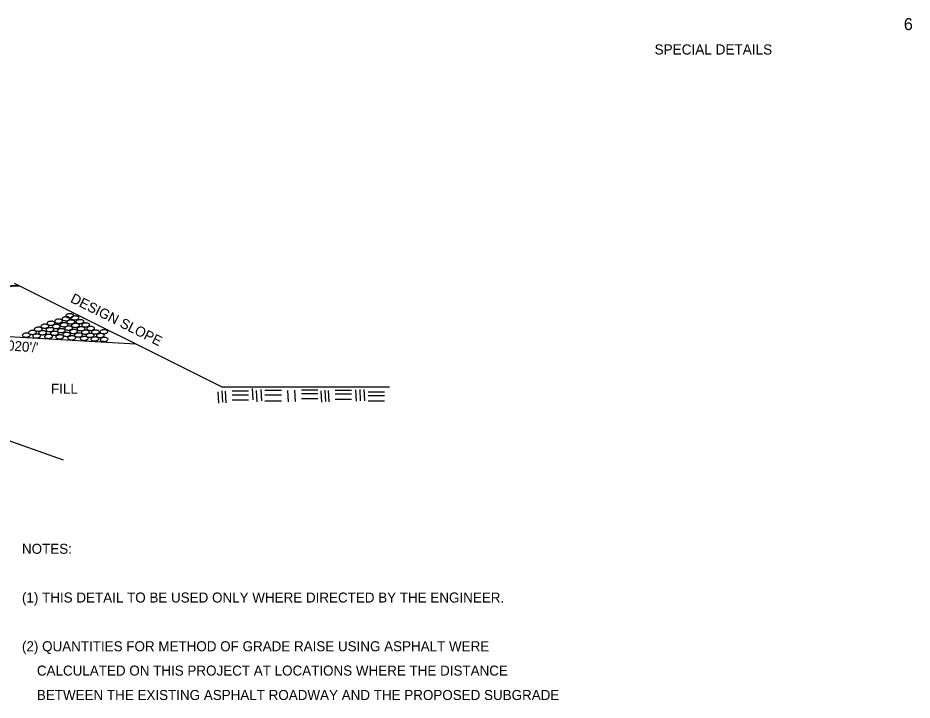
# Model space of a CAD drawing. Extents: x 3287 to 1767681, y -265 to 581440.
# Drawn here: x 3460.9 to 3567.9, y 19.6 to 101.2 of the extents above; entities that cross this region are included whole.
import ezdxf

# ---------------------------------------------------------------- set-up
doc = ezdxf.new("R2010")
doc.units = 0
for name, color, linetype in [('R_Border Notes', 7, 'Continuous'), ('R_Border PE', 7, 'Continuous'), ('R_Border Prem', 7, 'Continuous')]:
    doc.layers.add(name, color=color, linetype=linetype)

msp = doc.modelspace()

# ---------------------------------------------------------------- linework, layer by layer
at = {"layer": 'R_Border PE'}
for p, q in [((3331.63, 63.99), (3461.08, 69.15)), ((3331.8, 64.08), (3460.94, 69.23)), ((3485.32, 57.03), (3460.48, 69.45)), ((3444.21, 64.01), (3474.97, 62.21)), ((3431.52, 60.73), (3466.29, 48.36)), ((3505.34, 57.03), (3485.32, 57.03)), ((3488.92, 56.89), (3488.99, 55.54)), ((3489.95, 56.78), (3490.03, 55.42)), ((3501.28, 56.73), (3501.36, 55.38)), ((3501.77, 56.78), (3501.84, 55.43)), ((3502.28, 56.78), (3502.36, 55.43)), ((3484.81, 56.5), (3484.89, 55.15)), ((3485.28, 56.59), (3485.36, 55.24)), ((3485.69, 56.55), (3485.76, 55.19)), ((3488.47, 56.55), (3486.51, 56.55)), ((3488.47, 56.1), (3486.51, 56.1)), ((3489.37, 56.66), (3489.45, 55.31)), ((3492.4, 56.66), (3490.43, 56.66)), ((3492.4, 56.08), (3490.43, 56.08)), ((3493.12, 56.65), (3493.2, 55.29)), ((3493.99, 56.7), (3494.07, 55.34)), ((3496.78, 56.7), (3494.82, 56.7)), ((3496.78, 56.24), (3494.82, 56.24)), ((3496.78, 55.64), (3494.82, 55.64)), ((3497.13, 56.59), (3497.21, 55.24)), ((3497.6, 56.68), (3497.67, 55.33)), ((3498, 56.64), (3498.08, 55.28)), ((3500.79, 56.64), (3498.83, 56.64)), ((3500.79, 56.19), (3498.83, 56.19)), ((3504.74, 56.43), (3502.78, 56.43)), ((3504.74, 55.99), (3502.78, 55.99)), ((3488.47, 55.49), (3486.51, 55.49)), ((3492.4, 55.39), (3490.43, 55.39)), ((3500.79, 55.58), (3498.83, 55.58)), ((3504.74, 55.38), (3502.78, 55.38))]:
    msp.add_line(p, q, dxfattribs=at)
for points in [[(3466.63, 64.99), (3466.47, 65.01), (3466.27, 65.06), (3466.17, 65.15), (3466.16, 65.21), (3466.21, 65.31), (3466.26, 65.36), (3466.37, 65.42), (3466.53, 65.46), (3466.62, 65.46), (3466.74, 65.45), (3466.88, 65.44), (3466.99, 65.4), (3467.08, 65.3), (3467.1, 65.25), (3467.07, 65.15), (3466.99, 65.1), (3466.92, 65.06), (3466.8, 65.01), (3466.74, 64.99), (3466.63, 64.99)], [(3467.08, 65.36), (3466.91, 65.38), (3466.72, 65.43), (3466.63, 65.53), (3466.61, 65.58), (3466.66, 65.69), (3466.71, 65.73), (3466.82, 65.79), (3466.98, 65.83), (3467.06, 65.83), (3467.19, 65.83), (3467.33, 65.82), (3467.43, 65.76), (3467.54, 65.68), (3467.55, 65.61), (3467.52, 65.52), (3467.45, 65.46), (3467.37, 65.43), (3467.26, 65.39), (3467.19, 65.36), (3467.08, 65.36)], [(3467.72, 65.09), (3467.55, 65.11), (3467.35, 65.16), (3467.25, 65.26), (3467.24, 65.31), (3467.29, 65.41), (3467.35, 65.45), (3467.46, 65.52), (3467.62, 65.56), (3467.7, 65.56), (3467.83, 65.55), (3467.96, 65.54), (3468.07, 65.49), (3468.17, 65.41), (3468.18, 65.34), (3468.15, 65.26), (3468.08, 65.19), (3468, 65.15), (3467.89, 65.12), (3467.83, 65.1), (3467.72, 65.09)], [(3463.32, 63.74), (3463.15, 63.76), (3462.95, 63.81), (3462.86, 63.91), (3462.84, 63.97), (3462.89, 64.07), (3462.94, 64.11), (3463.05, 64.17), (3463.21, 64.22), (3463.3, 64.22), (3463.42, 64.21), (3463.56, 64.2), (3463.66, 64.14), (3463.77, 64.06), (3463.78, 63.99), (3463.76, 63.91), (3463.68, 63.84), (3463.61, 63.81), (3463.49, 63.77), (3463.42, 63.75), (3463.32, 63.74)], [(3464.12, 64.1), (3463.95, 64.12), (3463.75, 64.17), (3463.65, 64.26), (3463.64, 64.32), (3463.68, 64.42), (3463.75, 64.47), (3463.86, 64.54), (3464.02, 64.57), (3464.1, 64.57), (3464.22, 64.56), (3464.36, 64.55), (3464.47, 64.51), (3464.56, 64.41), (3464.58, 64.36), (3464.54, 64.26), (3464.47, 64.2), (3464.4, 64.17), (3464.3, 64.13), (3464.23, 64.11), (3464.12, 64.1)], [(3464.83, 64.45), (3464.67, 64.47), (3464.47, 64.53), (3464.38, 64.62), (3464.36, 64.68), (3464.41, 64.78), (3464.47, 64.83), (3464.57, 64.89), (3464.73, 64.92), (3464.82, 64.92), (3464.94, 64.93), (3465.08, 64.9), (3465.19, 64.85), (3465.29, 64.77), (3465.3, 64.71), (3465.28, 64.61), (3465.2, 64.55), (3465.13, 64.52), (3465.01, 64.48), (3464.94, 64.46), (3464.83, 64.45)], [(3465.48, 64.06), (3465.31, 64.08), (3465.12, 64.13), (3465.02, 64.23), (3465, 64.28), (3465.05, 64.39), (3465.11, 64.43), (3465.21, 64.5), (3465.37, 64.53), (3465.46, 64.53), (3465.59, 64.54), (3465.73, 64.52), (3465.83, 64.46), (3465.93, 64.38), (3465.94, 64.32), (3465.92, 64.22), (3465.84, 64.16), (3465.76, 64.12), (3465.65, 64.09), (3465.59, 64.07), (3465.48, 64.06)], [(3465.76, 64.71), (3465.59, 64.72), (3465.39, 64.78), (3465.29, 64.87), (3465.28, 64.93), (3465.33, 65.03), (3465.38, 65.08), (3465.49, 65.14), (3465.65, 65.18), (3465.74, 65.18), (3465.86, 65.17), (3466, 65.16), (3466.1, 65.12), (3466.2, 65.02), (3466.22, 64.96), (3466.18, 64.87), (3466.11, 64.81), (3466.03, 64.78), (3465.93, 64.73), (3465.86, 64.71), (3465.76, 64.71)], [(3466.42, 64.27), (3466.25, 64.29), (3466.05, 64.35), (3465.95, 64.43), (3465.94, 64.49), (3465.99, 64.59), (3466.04, 64.64), (3466.17, 64.7), (3466.32, 64.74), (3466.4, 64.74), (3466.53, 64.73), (3466.66, 64.72), (3466.77, 64.68), (3466.86, 64.58), (3466.88, 64.53), (3466.85, 64.43), (3466.78, 64.38), (3466.7, 64.34), (3466.6, 64.3), (3466.53, 64.28), (3466.42, 64.27)], [(3466.95, 63.87), (3466.79, 63.89), (3466.59, 63.95), (3466.49, 64.04), (3466.48, 64.1), (3466.53, 64.2), (3466.58, 64.24), (3466.69, 64.3), (3466.85, 64.35), (3466.93, 64.35), (3467.06, 64.34), (3467.2, 64.33), (3467.31, 64.27), (3467.41, 64.19), (3467.42, 64.12), (3467.39, 64.03), (3467.32, 63.97), (3467.24, 63.95), (3467.13, 63.9), (3467.06, 63.88), (3466.95, 63.87)], [(3467.22, 64.62), (3467.05, 64.63), (3466.85, 64.68), (3466.75, 64.78), (3466.74, 64.84), (3466.79, 64.94), (3466.85, 64.98), (3466.96, 65.04), (3467.12, 65.09), (3467.2, 65.09), (3467.33, 65.07), (3467.47, 65.07), (3467.57, 65.01), (3467.67, 64.93), (3467.68, 64.86), (3467.65, 64.78), (3467.57, 64.71), (3467.5, 64.68), (3467.4, 64.64), (3467.33, 64.62), (3467.22, 64.62)], [(3467.78, 64.19), (3467.61, 64.21), (3467.42, 64.26), (3467.32, 64.36), (3467.3, 64.41), (3467.35, 64.52), (3467.41, 64.56), (3467.52, 64.62), (3467.68, 64.67), (3467.76, 64.67), (3467.89, 64.65), (3468.03, 64.65), (3468.13, 64.59), (3468.23, 64.51), (3468.25, 64.44), (3468.22, 64.36), (3468.14, 64.29), (3468.07, 64.26), (3467.95, 64.22), (3467.89, 64.2), (3467.78, 64.19)], [(3468.32, 64.65), (3468.14, 64.67), (3467.95, 64.71), (3467.84, 64.81), (3467.83, 64.86), (3467.88, 64.97), (3467.94, 65.01), (3468.05, 65.08), (3468.21, 65.12), (3468.29, 65.12), (3468.42, 65.11), (3468.56, 65.1), (3468.67, 65.05), (3468.76, 64.97), (3468.78, 64.9), (3468.74, 64.81), (3468.67, 64.74), (3468.6, 64.71), (3468.49, 64.68), (3468.42, 64.65), (3468.32, 64.65)], [(3468.42, 64.27), (3468.6, 64.25), (3468.79, 64.2), (3468.9, 64.1), (3468.91, 64.05), (3468.86, 63.95), (3468.8, 63.9), (3468.68, 63.84), (3468.53, 63.8), (3468.44, 63.8), (3468.32, 63.81), (3468.18, 63.82), (3468.08, 63.86), (3467.98, 63.96), (3467.97, 64.02), (3468, 64.11), (3468.07, 64.17), (3468.14, 64.2), (3468.25, 64.24), (3468.32, 64.26), (3468.42, 64.27)], [(3468.98, 64.73), (3469.14, 64.71), (3469.34, 64.67), (3469.44, 64.57), (3469.46, 64.52), (3469.41, 64.41), (3469.35, 64.37), (3469.23, 64.3), (3469.08, 64.26), (3469, 64.26), (3468.87, 64.27), (3468.73, 64.28), (3468.62, 64.33), (3468.53, 64.42), (3468.52, 64.48), (3468.55, 64.57), (3468.62, 64.64), (3468.69, 64.67), (3468.8, 64.7), (3468.87, 64.73), (3468.98, 64.73)], [(3469.58, 64.31), (3469.75, 64.3), (3469.94, 64.24), (3470.05, 64.15), (3470.06, 64.1), (3470.01, 63.99), (3469.96, 63.95), (3469.84, 63.88), (3469.69, 63.84), (3469.6, 63.84), (3469.47, 63.85), (3469.33, 63.86), (3469.23, 63.91), (3469.13, 63.99), (3469.12, 64.07), (3469.15, 64.15), (3469.22, 64.22), (3469.29, 64.25), (3469.41, 64.28), (3469.47, 64.31), (3469.58, 64.31)], [(3461.88, 63.03), (3461.72, 63.05), (3461.52, 63.09), (3461.43, 63.2), (3461.41, 63.25), (3461.46, 63.36), (3461.51, 63.4), (3461.62, 63.46), (3461.79, 63.5), (3461.86, 63.5), (3461.99, 63.49), (3462.13, 63.48), (3462.24, 63.43), (3462.34, 63.35), (3462.35, 63.28), (3462.32, 63.19), (3462.25, 63.13), (3462.17, 63.09), (3462.06, 63.06), (3461.99, 63.03), (3461.88, 63.03)], [(3462.62, 63.36), (3462.45, 63.37), (3462.26, 63.42), (3462.16, 63.52), (3462.15, 63.57), (3462.2, 63.68), (3462.25, 63.72), (3462.36, 63.78), (3462.52, 63.82), (3462.6, 63.82), (3462.73, 63.82), (3462.87, 63.81), (3462.97, 63.76), (3463.07, 63.67), (3463.09, 63.61), (3463.06, 63.51), (3462.99, 63.46), (3462.9, 63.42), (3462.79, 63.37), (3462.73, 63.36), (3462.62, 63.36)], [(3463.13, 62.93), (3462.96, 62.95), (3462.76, 63), (3462.67, 63.09), (3462.65, 63.16), (3462.71, 63.26), (3462.75, 63.31), (3462.87, 63.36), (3463.03, 63.4), (3463.11, 63.4), (3463.23, 63.39), (3463.37, 63.38), (3463.48, 63.34), (3463.58, 63.25), (3463.6, 63.19), (3463.56, 63.09), (3463.49, 63.04), (3463.42, 63), (3463.3, 62.96), (3463.23, 62.94), (3463.13, 62.93)], [(3463.84, 63.32), (3463.67, 63.33), (3463.48, 63.38), (3463.38, 63.48), (3463.36, 63.53), (3463.42, 63.64), (3463.46, 63.68), (3463.58, 63.75), (3463.74, 63.79), (3463.82, 63.79), (3463.94, 63.78), (3464.08, 63.77), (3464.19, 63.72), (3464.29, 63.63), (3464.31, 63.57), (3464.28, 63.48), (3464.2, 63.42), (3464.13, 63.38), (3464.02, 63.34), (3463.94, 63.32), (3463.84, 63.32)], [(3464.55, 62.87), (3464.38, 62.89), (3464.19, 62.95), (3464.09, 63.04), (3464.08, 63.09), (3464.13, 63.2), (3464.18, 63.24), (3464.29, 63.31), (3464.45, 63.35), (3464.53, 63.35), (3464.66, 63.34), (3464.79, 63.33), (3464.9, 63.28), (3465, 63.2), (3465.02, 63.13), (3464.99, 63.04), (3464.91, 62.97), (3464.84, 62.94), (3464.72, 62.9), (3464.66, 62.88), (3464.55, 62.87)], [(3464.72, 63.69), (3464.54, 63.71), (3464.35, 63.76), (3464.26, 63.86), (3464.24, 63.91), (3464.29, 64.02), (3464.34, 64.07), (3464.46, 64.12), (3464.61, 64.16), (3464.7, 64.16), (3464.82, 64.15), (3464.96, 64.14), (3465.07, 64.1), (3465.17, 64.01), (3465.18, 63.95), (3465.15, 63.85), (3465.08, 63.8), (3465, 63.76), (3464.89, 63.72), (3464.82, 63.69), (3464.72, 63.69)], [(3465.27, 63.25), (3465.1, 63.27), (3464.9, 63.33), (3464.79, 63.42), (3464.78, 63.48), (3464.83, 63.58), (3464.89, 63.62), (3465, 63.69), (3465.16, 63.72), (3465.24, 63.72), (3465.37, 63.72), (3465.51, 63.7), (3465.61, 63.66), (3465.71, 63.57), (3465.73, 63.51), (3465.69, 63.42), (3465.62, 63.36), (3465.54, 63.32), (3465.44, 63.29), (3465.37, 63.26), (3465.27, 63.25)], [(3465.88, 63.29), (3466.04, 63.29), (3466.24, 63.22), (3466.34, 63.13), (3466.35, 63.07), (3466.3, 62.96), (3466.24, 62.92), (3466.14, 62.87), (3465.97, 62.82), (3465.89, 62.82), (3465.76, 62.83), (3465.63, 62.86), (3465.52, 62.9), (3465.43, 62.97), (3465.41, 63.04), (3465.44, 63.13), (3465.52, 63.19), (3465.59, 63.24), (3465.7, 63.27), (3465.77, 63.29), (3465.88, 63.29)], [(3466.08, 63.57), (3465.92, 63.58), (3465.72, 63.64), (3465.62, 63.73), (3465.61, 63.79), (3465.66, 63.89), (3465.72, 63.95), (3465.82, 64), (3465.98, 64.03), (3466.06, 64.03), (3466.19, 64.04), (3466.33, 64.02), (3466.43, 63.97), (3466.53, 63.88), (3466.55, 63.82), (3466.52, 63.72), (3466.44, 63.67), (3466.37, 63.63), (3466.26, 63.6), (3466.19, 63.57), (3466.08, 63.57)], [(3466.7, 63.59), (3466.87, 63.58), (3467.07, 63.52), (3467.17, 63.42), (3467.18, 63.36), (3467.13, 63.26), (3467.07, 63.22), (3466.96, 63.17), (3466.8, 63.12), (3466.72, 63.11), (3466.59, 63.13), (3466.46, 63.15), (3466.35, 63.2), (3466.25, 63.27), (3466.24, 63.34), (3466.27, 63.43), (3466.34, 63.49), (3466.41, 63.53), (3466.53, 63.57), (3466.6, 63.58), (3466.7, 63.59)], [(3467.32, 63.19), (3467.48, 63.17), (3467.68, 63.1), (3467.78, 63.02), (3467.8, 62.96), (3467.74, 62.86), (3467.68, 62.81), (3467.57, 62.74), (3467.42, 62.71), (3467.33, 62.71), (3467.21, 62.7), (3467.07, 62.73), (3466.96, 62.78), (3466.86, 62.86), (3466.85, 62.92), (3466.88, 63.02), (3466.95, 63.08), (3467.03, 63.11), (3467.14, 63.15), (3467.21, 63.17), (3467.32, 63.19)], [(3467.53, 63.93), (3467.7, 63.93), (3467.9, 63.85), (3468, 63.76), (3468.01, 63.7), (3467.96, 63.61), (3467.91, 63.56), (3467.8, 63.51), (3467.63, 63.47), (3467.55, 63.46), (3467.42, 63.47), (3467.29, 63.49), (3467.18, 63.53), (3467.08, 63.61), (3467.07, 63.67), (3467.1, 63.77), (3467.18, 63.83), (3467.25, 63.88), (3467.36, 63.91), (3467.43, 63.93), (3467.53, 63.93)], [(3468.11, 63.52), (3468.28, 63.51), (3468.48, 63.45), (3468.58, 63.36), (3468.6, 63.31), (3468.54, 63.2), (3468.49, 63.16), (3468.37, 63.08), (3468.22, 63.06), (3468.13, 63.06), (3468, 63.06), (3467.87, 63.07), (3467.76, 63.12), (3467.67, 63.21), (3467.65, 63.27), (3467.68, 63.36), (3467.76, 63.42), (3467.83, 63.46), (3467.94, 63.49), (3468, 63.51), (3468.11, 63.52)], [(3468.94, 63.86), (3469.11, 63.85), (3469.31, 63.79), (3469.42, 63.69), (3469.43, 63.64), (3469.38, 63.54), (3469.32, 63.5), (3469.2, 63.44), (3469.04, 63.39), (3468.96, 63.39), (3468.83, 63.4), (3468.7, 63.42), (3468.59, 63.46), (3468.5, 63.54), (3468.48, 63.61), (3468.52, 63.7), (3468.58, 63.76), (3468.65, 63.8), (3468.76, 63.84), (3468.83, 63.86), (3468.94, 63.86)], [(3469.51, 63.48), (3469.69, 63.47), (3469.88, 63.41), (3469.98, 63.32), (3469.99, 63.26), (3469.94, 63.16), (3469.88, 63.11), (3469.77, 63.06), (3469.62, 63.01), (3469.54, 63.01), (3469.41, 63.03), (3469.27, 63.03), (3469.17, 63.08), (3469.06, 63.17), (3469.05, 63.23), (3469.08, 63.32), (3469.16, 63.38), (3469.23, 63.42), (3469.34, 63.46), (3469.41, 63.48), (3469.51, 63.48)], [(3470.15, 63.88), (3470.31, 63.86), (3470.51, 63.81), (3470.61, 63.72), (3470.63, 63.66), (3470.57, 63.56), (3470.51, 63.51), (3470.4, 63.45), (3470.24, 63.41), (3470.16, 63.41), (3470.04, 63.42), (3469.9, 63.43), (3469.79, 63.48), (3469.7, 63.57), (3469.69, 63.63), (3469.71, 63.72), (3469.79, 63.78), (3469.86, 63.81), (3469.97, 63.86), (3470.04, 63.88), (3470.15, 63.88)], [(3470.74, 63.46), (3470.9, 63.45), (3471.1, 63.39), (3471.2, 63.3), (3471.21, 63.24), (3471.16, 63.14), (3471.11, 63.09), (3471, 63.04), (3470.84, 62.99), (3470.76, 62.99), (3470.63, 63), (3470.49, 63.02), (3470.39, 63.06), (3470.29, 63.14), (3470.27, 63.21), (3470.3, 63.3), (3470.38, 63.36), (3470.46, 63.4), (3470.56, 63.44), (3470.63, 63.46), (3470.74, 63.46)], [(3471.18, 63.44), (3471.01, 63.46), (3470.82, 63.51), (3470.72, 63.61), (3470.7, 63.66), (3470.76, 63.77), (3470.81, 63.81), (3470.92, 63.87), (3471.07, 63.91), (3471.16, 63.91), (3471.29, 63.91), (3471.43, 63.89), (3471.53, 63.84), (3471.63, 63.76), (3471.65, 63.69), (3471.62, 63.6), (3471.54, 63.54), (3471.47, 63.51), (3471.35, 63.47), (3471.29, 63.44), (3471.18, 63.44)], [(3468.81, 63.11), (3468.98, 63.09), (3469.17, 63.04), (3469.27, 62.95), (3469.29, 62.89), (3469.23, 62.79), (3469.18, 62.74), (3469.06, 62.69), (3468.91, 62.64), (3468.83, 62.64), (3468.71, 62.65), (3468.56, 62.66), (3468.46, 62.71), (3468.36, 62.8), (3468.34, 62.86), (3468.37, 62.95), (3468.45, 63.01), (3468.52, 63.05), (3468.64, 63.08), (3468.71, 63.1), (3468.81, 63.11)], [(3470.07, 63.05), (3470.24, 63.04), (3470.44, 62.97), (3470.53, 62.88), (3470.55, 62.82), (3470.5, 62.72), (3470.45, 62.68), (3470.34, 62.62), (3470.18, 62.57), (3470.09, 62.57), (3469.97, 62.58), (3469.83, 62.6), (3469.72, 62.64), (3469.62, 62.73), (3469.6, 62.79), (3469.64, 62.88), (3469.71, 62.94), (3469.79, 62.98), (3469.9, 63.03), (3469.97, 63.04), (3470.07, 63.05)], [(3471.19, 62.98), (3471.36, 62.98), (3471.56, 62.91), (3471.65, 62.82), (3471.67, 62.77), (3471.62, 62.66), (3471.57, 62.62), (3471.46, 62.56), (3471.29, 62.52), (3471.2, 62.51), (3471.08, 62.53), (3470.95, 62.55), (3470.84, 62.58), (3470.74, 62.67), (3470.72, 62.73), (3470.76, 62.82), (3470.83, 62.89), (3470.9, 62.93), (3471.02, 62.96), (3471.09, 62.98), (3471.19, 62.98)]]:
    msp.add_spline(points, degree=3, dxfattribs=at)

# ---------------------------------------------------------------- texts
at = {"layer": 'R_Border Notes'}
msp.add_text('SPECIAL DETAILS', height=1.2132, dxfattribs=at).set_placement((3537.05, 96.84))
at = {"layer": 'R_Border PE'}
for s, rotation, p in [('DESIGN SLOPE', 333.435, (3467.07, 67.26)), ("0.020'/'", 355.6232, (3458.21, 61.56))]:
    msp.add_text(s, height=1.2, rotation=rotation, dxfattribs=at).set_placement(p)
for s, p in [('FILL', (3464.85, 56.25)), ('NOTES:', (3461.37, 37.11)), ('(1) THIS DETAIL TO BE USED ONLY WHERE DIRECTED BY THE ENGINEER.', (3461.37, 31.28)), ('(2) QUANTITIES FOR METHOD OF GRADE RAISE USING ASPHALT WERE', (3461.37, 25.45)), ('    CALCULATED ON THIS PROJECT AT LOCATIONS WHERE THE DISTANCE', (3461.37, 22.54)), ('    BETWEEN THE EXISTING ASPHALT ROADWAY AND THE PROPOSED SUBGRADE', (3461.37, 19.62))]:
    msp.add_text(s, height=1.2, dxfattribs=at).set_placement(p)
at = {"layer": 'R_Border Prem'}
msp.add_text('6', height=1.44, dxfattribs=at).set_placement((3566.87, 99.76))

doc.saveas('drawing.dxf')
